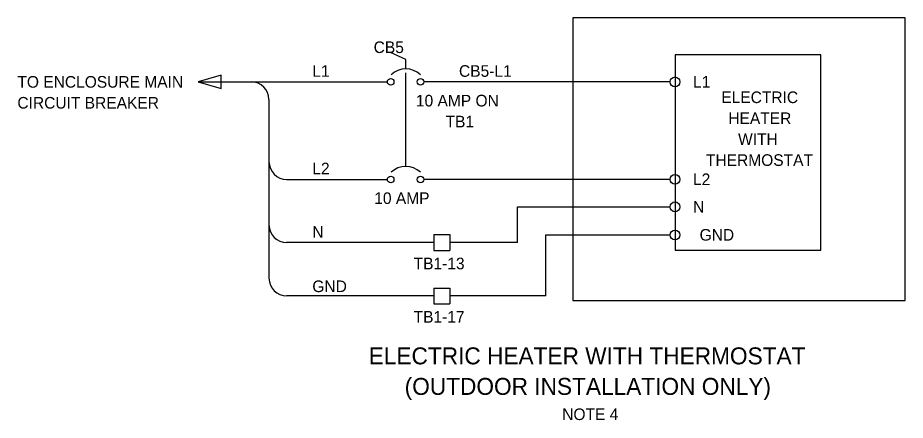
# Model space of a CAD drawing. Extents: x -0.472 to 0.292, y 0.036 to 0.383.
import ezdxf

# ---------------------------------------------------------------- set-up
doc = ezdxf.new("R2010")
doc.units = 0
for name, color, linetype in [('Default', 7, 'Continuous'), ('HS_Dimensions_and_Text', 7, 'Continuous'), ('HS_Electrical_Cable', 7, 'Continuous'), ('HS_Electrical_Devices', 7, 'Continuous'), ('HS_Electrical_Enclosure', 7, 'Continuous')]:
    doc.layers.add(name, color=color, linetype=linetype)

# ---------------------------------------------------------------- blocks, each defined once
blk = doc.blocks.new('ARROW')
at = {"layer": 'Default'}
blk.add_lwpolyline([(0, 0), (-0.00556, 0.00159), (-0.00556, -0.00159)], close=True, dxfattribs=at)

msp = doc.modelspace()

# ---------------------------------------------------------------- linework, layer by layer
at = {"layer": 'HS_Dimensions_and_Text'}
msp.add_lwpolyline([(0.00555, 0.13929), (0.29177, 0.13929), (0.29177, 0.38252), (0.00555, 0.38252)], close=True, dxfattribs=at)
at = {"layer": 'HS_Electrical_Cable'}
for p, q in [((-0.31683, 0.32739), (-0.17671, 0.32739)), ((-0.17671, 0.32739), (-0.15395, 0.32739)), ((0.0894, 0.32739), (-0.12268, 0.32739)), ((-0.25586, 0.31222), (-0.25586, 0.15846)), ((-0.24069, 0.24352), (-0.15395, 0.24352)), ((0.0894, 0.24352), (-0.12268, 0.24352)), ((-0.04195, 0.18916), (-0.04195, 0.21991)), ((-0.04195, 0.21991), (0.0894, 0.21991)), ((-0.01759, 0.1433), (-0.01759, 0.19576)), ((-0.01759, 0.19576), (0.0894, 0.19576)), ((-0.11394, 0.18916), (-0.24069, 0.18916)), ((-0.04195, 0.18916), (-0.10029, 0.18916)), ((-0.11394, 0.1433), (-0.24069, 0.1433)), ((-0.01759, 0.1433), (-0.10029, 0.1433))]:
    msp.add_line(p, q, dxfattribs=at)
for centre, start, end in [((-0.27103, 0.31222), 360, 90), ((-0.24069, 0.25869), 180, 270), ((-0.24069, 0.20433), 180, 270), ((-0.24069, 0.15846), 180, 270)]:
    msp.add_arc(centre, 0.01517, start, end, dxfattribs=at)
at = {"layer": 'HS_Electrical_Devices'}
for p, q in [((-0.1381, 0.34668), (-0.15131, 0.35277)), ((-0.1381, 0.33856), (-0.1381, 0.34668)), ((-0.1381, 0.2547), (-0.1381, 0.33513)), ((-0.11394, 0.19599), (-0.10029, 0.19599)), ((-0.11394, 0.19599), (-0.11394, 0.18234)), ((-0.10029, 0.19599), (-0.10029, 0.18234)), ((-0.11394, 0.18234), (-0.10029, 0.18234)), ((-0.11394, 0.15012), (-0.10029, 0.15012)), ((-0.11394, 0.15012), (-0.11394, 0.13647)), ((-0.10029, 0.15012), (-0.10029, 0.13647)), ((-0.11394, 0.13647), (-0.10029, 0.13647))]:
    msp.add_line(p, q, dxfattribs=at)
for centre, radius in [((-0.15111, 0.32739), 0.00284), ((-0.12552, 0.32739), 0.00284), ((0.09362, 0.32739), 0.00422), ((-0.15111, 0.24352), 0.00284), ((-0.12552, 0.24352), 0.00284), ((0.09362, 0.24352), 0.00422), ((0.09362, 0.21991), 0.00422), ((0.09362, 0.19576), 0.00422)]:
    msp.add_circle(centre, radius, dxfattribs=at)
for centre in [(-0.1381, 0.32017), (-0.1381, 0.2363)]:
    msp.add_arc(centre, 0.0184, 46.35835, 133.64165, dxfattribs=at)
at = {"layer": 'HS_Electrical_Enclosure'}
msp.add_lwpolyline([(0.09362, 0.18259), (0.2192, 0.18259), (0.2192, 0.35066), (0.09362, 0.35066)], close=True, dxfattribs=at)

# ---------------------------------------------------------------- block references
at = {"layer": 'HS_Electrical_Cable', "xscale": 3.5827662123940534, "yscale": 3.582766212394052, "rotation": 179.99999999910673}
msp.add_blockref('ARROW', (-0.31683, 0.32739), dxfattribs=at)

# ---------------------------------------------------------------- texts
at = {"layer": 'HS_Dimensions_and_Text'}
for s, p in [('CB5', (-0.16578, 0.3522)), ('L1', (-0.21856, 0.33173)), ('CB5-L1', (-0.09234, 0.33173)), ('TO ENCLOSURE MAIN ', (-0.47242, 0.32239)), ('L1', (0.1091, 0.32246)), ('CIRCUIT BREAKER', (-0.47242, 0.30439)), ('10 AMP ON ', (-0.12941, 0.30624)), ('ELECTRIC', (0.13345, 0.30913)), ('TB1', (-0.10388, 0.28824)), ('HEATER', (0.1395, 0.29113)), ('WITH ', (0.14788, 0.27313)), ('THERMOSTAT', (0.12024, 0.25513)), ('L2', (-0.21856, 0.24786)), ('L2', (0.1091, 0.2386)), ('10 AMP', (-0.16525, 0.22237)), ('N', (0.1091, 0.21499)), ('N', (-0.21856, 0.19331)), ('GND', (0.11477, 0.19083)), ('TB1-13', (-0.13137, 0.1662)), ('GND', (-0.21856, 0.14658)), ('TB1-17', (-0.13137, 0.12034))]:
    msp.add_text(s, height=0.01, rotation=360, dxfattribs=at).set_placement(p)
for s, height, p in [('ELECTRIC HEATER WITH THERMOSTAT', 0.0145833, (-0.17005, 0.08446)), ('(OUTDOOR INSTALLATION ONLY)', 0.0145833, (-0.1391, 0.05821)), ('NOTE 4', 0.01, (-0.00348, 0.03654))]:
    msp.add_text(s, height=height, dxfattribs=at).set_placement(p)

doc.saveas('drawing.dxf')
